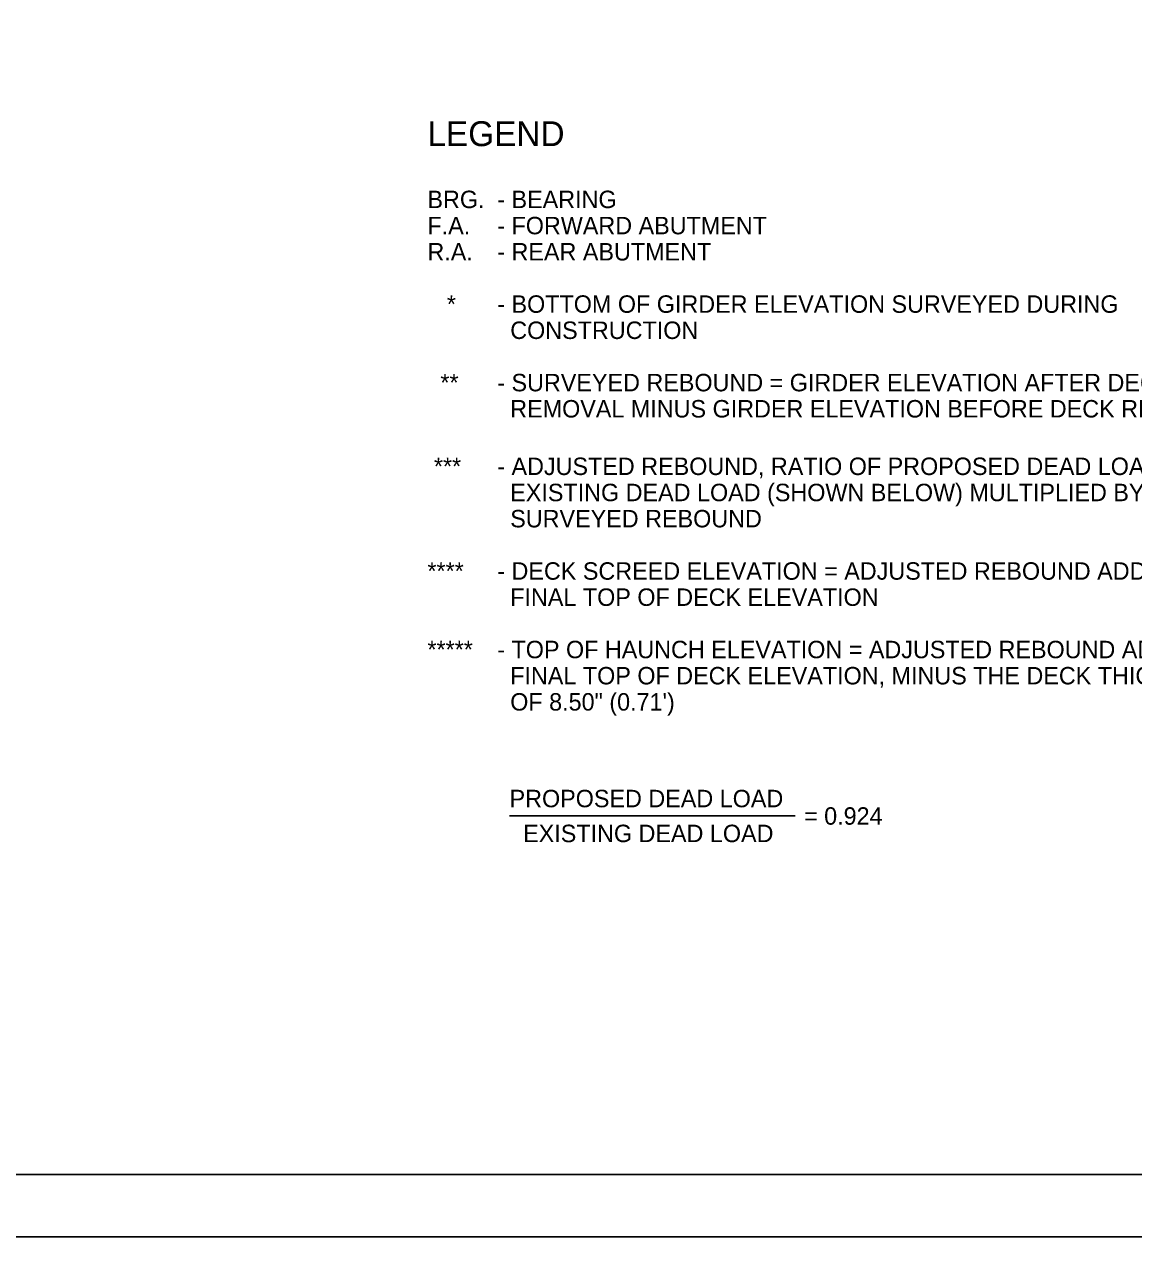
# Model space of a CAD drawing. Extents: x 0 to 34, y 0 to 22.
# Drawn here: x 20.39 to 29.29, y 0 to 9.73 of the extents above; entities that cross this region are included whole.
import ezdxf

# ---------------------------------------------------------------- set-up
doc = ezdxf.new("R2010")
doc.units = 0
for name, color, linetype in [('BR_P_Gen_Text', 7, 'Continuous'), ('SH_Border', 7, 'Continuous'), ('SH_Cut_Line', 7, 'Continuous')]:
    doc.layers.add(name, color=color, linetype=linetype)

msp = doc.modelspace()

# ---------------------------------------------------------------- linework, layer by layer
at = {"layer": 'BR_P_Gen_Text'}
msp.add_line((24.2817, 3.3762), (26.5734, 3.3762), dxfattribs=at)
at = {"layer": 'SH_Border'}
msp.add_lwpolyline([(1.5, 21.5), (33.5, 21.5), (33.5, 0.5), (1.5, 0.5)], close=True, dxfattribs=at)
at = {"layer": 'SH_Cut_Line'}
msp.add_lwpolyline([(0, 0), (34, 0), (34, 22), (0, 22)], close=True, dxfattribs=at)

# ---------------------------------------------------------------- texts
at = {"layer": 'BR_P_Gen_Text'}
for s, height, p in [('LEGEND', 0.2, (23.6229, 8.7508)), ('BRG.', 0.14, (23.6229, 8.2537)), ('- BEARING', 0.14, (24.1829, 8.2537)), ('F.A.', 0.14, (23.6229, 8.0437)), ('- FORWARD ABUTMENT', 0.14, (24.1829, 8.0437)), ('R.A.', 0.14, (23.6229, 7.8337)), ('- REAR ABUTMENT', 0.14, (24.1829, 7.8337)), ('   *', 0.14, (23.6229, 7.4137)), ('- BOTTOM OF GIRDER ELEVATION SURVEYED DURING ', 0.14, (24.1829, 7.4137)), ('  CONSTRUCTION', 0.14, (24.1829, 7.2037)), ('  **', 0.14, (23.6229, 6.7837)), ('- SURVEYED REBOUND = GIRDER ELEVATION AFTER DECK ', 0.14, (24.1829, 6.7837)), ('  REMOVAL MINUS GIRDER ELEVATION BEFORE DECK REMOVAL', 0.14, (24.1829, 6.5737)), (' ***', 0.14, (23.6229, 6.112)), ('- ADJUSTED REBOUND, RATIO OF PROPOSED DEAD LOAD TO', 0.14, (24.1829, 6.112)), ('  EXISTING DEAD LOAD (SHOWN BELOW) MULTIPLIED BY THE', 0.14, (24.1829, 5.902)), ('  SURVEYED REBOUND', 0.14, (24.1829, 5.692)), ('****', 0.14, (23.6229, 5.272)), ('- DECK SCREED ELEVATION = ADJUSTED REBOUND ADDED TO THE', 0.14, (24.1829, 5.272)), ('  FINAL TOP OF DECK ELEVATION', 0.14, (24.1829, 5.062)), ('*****', 0.14, (23.6229, 4.642)), ('- TOP OF HAUNCH ELEVATION = ADJUSTED REBOUND ADDED TO THE', 0.14, (24.1829, 4.642)), ('  FINAL TOP OF DECK ELEVATION, MINUS THE DECK THICKNESS', 0.14, (24.1829, 4.432)), ('  OF 8.50" (0.71\')', 0.14, (24.1829, 4.222)), ('PROPOSED DEAD LOAD', 0.14, (24.2817, 3.4462)), ('= 0.924', 0.14, (26.6434, 3.3062)), ('EXISTING DEAD LOAD', 0.14, (24.3903, 3.1662))]:
    msp.add_text(s, height=height, dxfattribs=at).set_placement(p)

doc.saveas('drawing.dxf')
